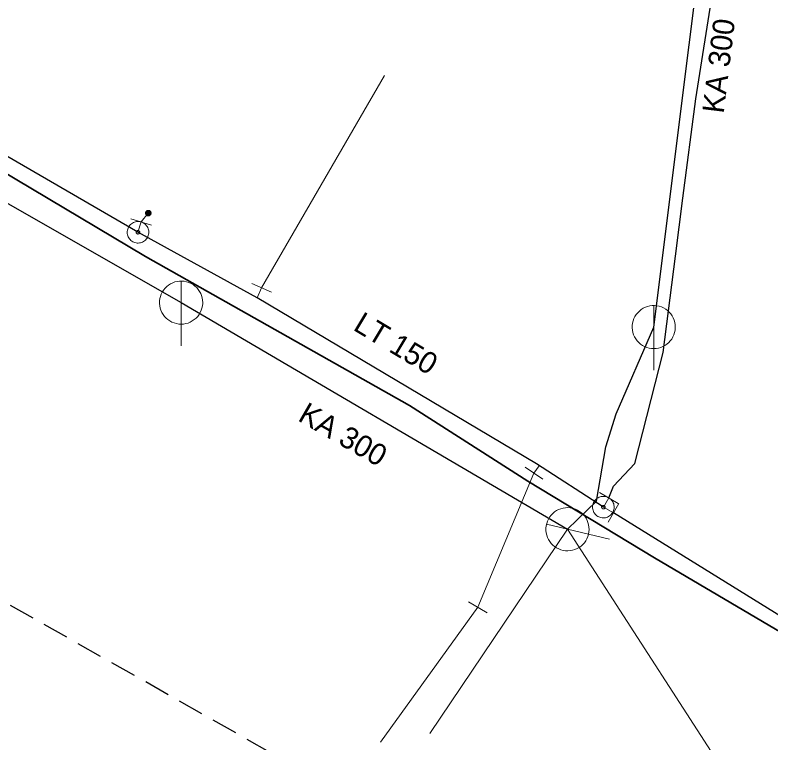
# Model space of a CAD drawing. Extents: x -749365 to -748625, y -965388 to -964881.
# Drawn here: x -749135.59 to -749100.56, y -965043.5 to -965009.76 of the extents above; entities that cross this region are included whole.
import ezdxf

# ---------------------------------------------------------------- set-up
doc = ezdxf.new("R2010")
doc.units = 0
doc.header["$LTSCALE"] = 0.4
doc.linetypes.add('MEDIUM_DASHED', pattern=[4.5, 3, -1.5])
for name, color, linetype, lineweight in [('1', 7, 'MEDIUM_DASHED', 25), ('11', 7, 'Continuous', 13), ('13', 7, 'Continuous', 13), ('14', 7, 'Continuous', 13), ('17', 7, 'Continuous', 25), ('22', 7, 'Continuous', 13), ('34', 7, 'Continuous', 13), ('47', 7, 'Continuous', 13), ('9', 7, 'Continuous', 13)]:
    doc.layers.add(name, color=color, linetype=linetype, lineweight=lineweight)

msp = doc.modelspace()

# ---------------------------------------------------------------- linework, layer by layer
at = {"layer": '1'}
msp.add_lwpolyline([(-748913.896, -965162.751), (-749358.2, -964911.234)], dxfattribs=at)
at = {"layer": '11'}
msp.add_line((-749116.373, -965043.072), (-749109.991, -965033.596), dxfattribs=at)
msp.add_lwpolyline([(-749073.956, -965068.175), (-749091.124, -965052.583), (-749101.388, -965046.912), (-749109.991, -965033.596)], dxfattribs=at)
at = {"layer": '13'}
for p, q in [((-749124.169, -965022.406), (-749118.474, -965012.556)), ((-749111.543, -965031.002), (-749114.141, -965037.213)), ((-749114.141, -965037.213), (-749118.651, -965043.467))]:
    msp.add_line(p, q, dxfattribs=at)
at = {"layer": '14'}
for p, q in [((-749129.75, -965019.352), (-749129.418, -965018.941)), ((-749129.897, -965019.83), (-749129.75, -965019.352)), ((-749124.372, -965022.863), (-749124.169, -965022.406)), ((-749111.304, -965030.651), (-749111.543, -965031.002)), ((-749108.327, -965032.572), (-749108.07, -965032.143)), ((-749108.327, -965032.572), (-749107.856, -965032.835))]:
    msp.add_line(p, q, dxfattribs=at)
at = {"layer": '14', "lineweight": 25}
msp.add_line((-749127.898, -965023.089), (-749109.991, -965033.596), dxfattribs=at)
for points in [[(-749180.034, -964993.011), (-749170.903, -964998.5), (-749127.898, -965023.089)], [(-749105.991, -965024.225), (-749102.71, -964998.031), (-749102.181, -964995.65)], [(-749109.991, -965033.596), (-749108.644, -965032.295), (-749108.214, -965029.781), (-749107.737, -965028.247), (-749105.991, -965024.225)]]:
    msp.add_lwpolyline(points, dxfattribs=at)
at = {"layer": '17'}
for points in [[(-749129.897, -965019.83), (-749141.763, -965012.953), (-749147.67, -965009.555), (-749169.498, -964996.566), (-749174.36, -964993.689), (-749178.686, -964991.22), (-749181.107, -964990.017), (-749187.92, -964986.181), (-749197.61, -964980.691), (-749208.557, -964974.308), (-749219.081, -964968.169), (-749222.514, -964968.719), (-749229.989, -964964.651), (-749252.214, -964952.116), (-749254.966, -964950.395)], [(-749108.07, -965032.143), (-749107.854, -965031.594), (-749106.861, -965030.548), (-749105.556, -965025.399), (-749104.984, -965020.942), (-749104.639, -965018.254), (-749104.048, -965013.641), (-749102.439, -965003.464), (-749102.25, -965001.809), (-749101.848, -964998.641), (-749101.001, -964988.296)], [(-749108.327, -965032.572), (-749111.431, -965030.569), (-749124.372, -965022.863), (-749129.897, -965019.83)], [(-749027.381, -965079.535), (-749031.869, -965076.931), (-749049.479, -965066.729), (-749061.789, -965059.449), (-749067.474, -965056.055), (-749068.21, -965055.686), (-749076.839, -965050.738), (-749082.197, -965048.039), (-749087.923, -965044.562), (-749096.879, -965039.45), (-749099.415, -965038.059), (-749107.856, -965032.835)]]:
    msp.add_lwpolyline(points, dxfattribs=at)
at = {"layer": '17', "lineweight": 35}
msp.add_lwpolyline([(-749218.876, -964969.25), (-749196.521, -964982.106), (-749183.951, -964989.517), (-749175.703, -964993.951), (-749141.565, -965013.806), (-749129.553, -965020.95), (-749117.313, -965027.865), (-749111.826, -965031.374), (-749105.952, -965034.92), (-749090.077, -965044.286), (-749082.192, -965048.943), (-749077.271, -965051.641), (-749068.54, -965056.298), (-749056.263, -965063.706)], dxfattribs=at)
at = {"layer": '22'}
for p, q in [((-749127.898, -965025.089), (-749127.897, -965022.089)), ((-749105.991, -965026.225), (-749105.99, -965023.225)), ((-749108.044, -965034.058), (-749110.963, -965033.364))]:
    msp.add_line(p, q, dxfattribs=at)
for points in [[(-749126.898, -965023.089), (-749126.903, -965022.98), (-749126.921, -965022.872), (-749126.951, -965022.766), (-749126.991, -965022.665), (-749127.043, -965022.568), (-749127.105, -965022.478), (-749127.177, -965022.395), (-749127.257, -965022.321), (-749127.345, -965022.255), (-749127.439, -965022.2), (-749127.539, -965022.155), (-749127.644, -965022.122), (-749127.751, -965022.1), (-749127.86, -965022.09), (-749127.97, -965022.092), (-749128.078, -965022.106), (-749128.185, -965022.131), (-749128.288, -965022.168), (-749128.386, -965022.217), (-749128.478, -965022.275), (-749128.564, -965022.344), (-749128.641, -965022.421), (-749128.71, -965022.507), (-749128.769, -965022.599), (-749128.817, -965022.697), (-749128.854, -965022.8), (-749128.88, -965022.907), (-749128.894, -965023.015), (-749128.897, -965023.125), (-749128.887, -965023.234), (-749128.866, -965023.341), (-749128.832, -965023.445), (-749128.788, -965023.545), (-749128.733, -965023.64), (-749128.667, -965023.728), (-749128.593, -965023.808), (-749128.51, -965023.88), (-749128.42, -965023.942), (-749128.324, -965023.994), (-749128.222, -965024.035), (-749128.117, -965024.065), (-749128.009, -965024.083), (-749127.899, -965024.089), (-749127.79, -965024.083), (-749127.682, -965024.065), (-749127.577, -965024.036), (-749127.475, -965023.995), (-749127.378, -965023.943), (-749127.288, -965023.881), (-749127.205, -965023.81), (-749127.13, -965023.73), (-749127.065, -965023.642), (-749127.009, -965023.548), (-749126.965, -965023.448), (-749126.931, -965023.344), (-749126.909, -965023.236), (-749126.899, -965023.127)], [(-749104.991, -965024.225), (-749104.996, -965024.116), (-749105.014, -965024.008), (-749105.044, -965023.902), (-749105.084, -965023.801), (-749105.136, -965023.704), (-749105.198, -965023.614), (-749105.27, -965023.531), (-749105.35, -965023.457), (-749105.438, -965023.391), (-749105.532, -965023.336), (-749105.632, -965023.291), (-749105.737, -965023.258), (-749105.844, -965023.236), (-749105.953, -965023.226), (-749106.063, -965023.228), (-749106.171, -965023.242), (-749106.278, -965023.267), (-749106.381, -965023.304), (-749106.479, -965023.353), (-749106.571, -965023.411), (-749106.657, -965023.48), (-749106.734, -965023.557), (-749106.803, -965023.643), (-749106.862, -965023.735), (-749106.91, -965023.833), (-749106.947, -965023.936), (-749106.973, -965024.043), (-749106.987, -965024.151), (-749106.99, -965024.261), (-749106.98, -965024.37), (-749106.959, -965024.477), (-749106.925, -965024.581), (-749106.881, -965024.681), (-749106.826, -965024.776), (-749106.76, -965024.864), (-749106.686, -965024.944), (-749106.603, -965025.016), (-749106.513, -965025.078), (-749106.417, -965025.13), (-749106.315, -965025.171), (-749106.21, -965025.201), (-749106.102, -965025.219), (-749105.992, -965025.225), (-749105.883, -965025.219), (-749105.775, -965025.201), (-749105.67, -965025.172), (-749105.568, -965025.131), (-749105.471, -965025.079), (-749105.381, -965025.017), (-749105.298, -965024.946), (-749105.223, -965024.866), (-749105.158, -965024.778), (-749105.102, -965024.684), (-749105.058, -965024.584), (-749105.024, -965024.48), (-749105.002, -965024.372), (-749104.992, -965024.263)], [(-749109.759, -965032.623), (-749109.866, -965032.603), (-749109.975, -965032.596), (-749110.086, -965032.601), (-749110.193, -965032.616), (-749110.299, -965032.644), (-749110.401, -965032.684), (-749110.499, -965032.735), (-749110.589, -965032.795), (-749110.674, -965032.866), (-749110.749, -965032.944), (-749110.816, -965033.031), (-749110.872, -965033.126), (-749110.918, -965033.225), (-749110.953, -965033.329), (-749110.977, -965033.436), (-749110.988, -965033.544), (-749110.989, -965033.654), (-749110.976, -965033.763), (-749110.951, -965033.87), (-749110.916, -965033.973), (-749110.869, -965034.072), (-749110.812, -965034.165), (-749110.744, -965034.252), (-749110.668, -965034.331), (-749110.584, -965034.4), (-749110.492, -965034.46), (-749110.394, -965034.51), (-749110.293, -965034.548), (-749110.186, -965034.576), (-749110.078, -965034.591), (-749109.969, -965034.596), (-749109.86, -965034.587), (-749109.752, -965034.567), (-749109.647, -965034.535), (-749109.546, -965034.492), (-749109.451, -965034.438), (-749109.362, -965034.374), (-749109.281, -965034.301), (-749109.208, -965034.219), (-749109.145, -965034.13), (-749109.091, -965034.034), (-749109.049, -965033.933), (-749109.017, -965033.828), (-749108.998, -965033.72), (-749108.991, -965033.611), (-749108.994, -965033.502), (-749109.011, -965033.394), (-749109.039, -965033.287), (-749109.078, -965033.185), (-749109.128, -965033.088), (-749109.189, -965032.997), (-749109.259, -965032.913), (-749109.338, -965032.837), (-749109.425, -965032.771), (-749109.518, -965032.714), (-749109.618, -965032.667), (-749109.722, -965032.632)]]:
    msp.add_lwpolyline(points, close=True, dxfattribs=at)
at = {"layer": '34'}
for p, q in [((-749130.228, -965019.206), (-749129.272, -965019.498)), ((-749124.626, -965022.203), (-749123.712, -965022.609)), ((-749111.129, -965031.282), (-749111.956, -965030.72)), ((-749108.499, -965031.886), (-749107.641, -965032.4)), ((-749107.612, -965032.398), (-749108.1, -965033.271)), ((-749114.572, -965036.96), (-749113.709, -965037.466))]:
    msp.add_line(p, q, dxfattribs=at)
at = {"layer": '47'}
for points in [[(-749130.335, -965019.589), (-749130.357, -965019.636), (-749130.375, -965019.685), (-749130.387, -965019.736), (-749130.395, -965019.788), (-749130.396, -965019.84), (-749130.392, -965019.893), (-749130.382, -965019.944), (-749130.368, -965019.994), (-749130.349, -965020.042), (-749130.324, -965020.089), (-749130.294, -965020.132), (-749130.26, -965020.172), (-749130.223, -965020.208), (-749130.181, -965020.24), (-749130.137, -965020.268), (-749130.09, -965020.29), (-749130.041, -965020.308), (-749129.989, -965020.32), (-749129.938, -965020.328), (-749129.886, -965020.329), (-749129.833, -965020.325), (-749129.781, -965020.316), (-749129.731, -965020.301), (-749129.683, -965020.282), (-749129.637, -965020.257), (-749129.594, -965020.227), (-749129.553, -965020.194), (-749129.518, -965020.156), (-749129.486, -965020.114), (-749129.458, -965020.07), (-749129.436, -965020.023), (-749129.418, -965019.974), (-749129.405, -965019.923), (-749129.398, -965019.871), (-749129.397, -965019.819), (-749129.4, -965019.767), (-749129.409, -965019.715), (-749129.424, -965019.665), (-749129.444, -965019.616), (-749129.469, -965019.57), (-749129.499, -965019.527), (-749129.532, -965019.487), (-749129.57, -965019.451), (-749129.612, -965019.419), (-749129.656, -965019.391), (-749129.703, -965019.369), (-749129.752, -965019.351), (-749129.802, -965019.338), (-749129.855, -965019.331), (-749129.907, -965019.33), (-749129.959, -965019.333), (-749130.01, -965019.343), (-749130.061, -965019.357), (-749130.109, -965019.377), (-749130.156, -965019.402), (-749130.199, -965019.432), (-749130.238, -965019.465), (-749130.275, -965019.503), (-749130.307, -965019.545)], [(-749129.968, -965019.79), (-749129.973, -965019.798), (-749129.975, -965019.806), (-749129.977, -965019.814), (-749129.978, -965019.822), (-749129.978, -965019.831), (-749129.977, -965019.84), (-749129.976, -965019.848), (-749129.974, -965019.857), (-749129.97, -965019.864), (-749129.967, -965019.872), (-749129.962, -965019.879), (-749129.956, -965019.886), (-749129.95, -965019.891), (-749129.944, -965019.897), (-749129.936, -965019.901), (-749129.928, -965019.906), (-749129.92, -965019.908), (-749129.912, -965019.91), (-749129.904, -965019.911), (-749129.895, -965019.911), (-749129.886, -965019.91), (-749129.878, -965019.909), (-749129.869, -965019.907), (-749129.861, -965019.904), (-749129.854, -965019.9), (-749129.847, -965019.895), (-749129.84, -965019.889), (-749129.835, -965019.883), (-749129.829, -965019.877), (-749129.825, -965019.869), (-749129.82, -965019.861), (-749129.818, -965019.853), (-749129.816, -965019.845), (-749129.815, -965019.837), (-749129.815, -965019.828), (-749129.815, -965019.82), (-749129.817, -965019.811), (-749129.819, -965019.802), (-749129.822, -965019.794), (-749129.826, -965019.787), (-749129.831, -965019.78), (-749129.837, -965019.773), (-749129.843, -965019.768), (-749129.849, -965019.762), (-749129.857, -965019.758), (-749129.865, -965019.753), (-749129.873, -965019.751), (-749129.881, -965019.749), (-749129.889, -965019.748), (-749129.898, -965019.748), (-749129.906, -965019.748), (-749129.915, -965019.75), (-749129.924, -965019.752), (-749129.931, -965019.756), (-749129.939, -965019.759), (-749129.946, -965019.764), (-749129.953, -965019.77), (-749129.958, -965019.776), (-749129.964, -965019.782)], [(-749108.069, -965032.143), (-749108.115, -965032.119), (-749108.164, -965032.099), (-749108.214, -965032.085), (-749108.265, -965032.075), (-749108.318, -965032.072), (-749108.371, -965032.074), (-749108.422, -965032.082), (-749108.473, -965032.094), (-749108.522, -965032.112), (-749108.569, -965032.134), (-749108.614, -965032.162), (-749108.655, -965032.195), (-749108.692, -965032.231), (-749108.726, -965032.271), (-749108.755, -965032.314), (-749108.779, -965032.36), (-749108.799, -965032.409), (-749108.814, -965032.46), (-749108.823, -965032.51), (-749108.826, -965032.563), (-749108.824, -965032.616), (-749108.817, -965032.668), (-749108.804, -965032.719), (-749108.787, -965032.768), (-749108.764, -965032.814), (-749108.736, -965032.859), (-749108.703, -965032.9), (-749108.667, -965032.937), (-749108.627, -965032.971), (-749108.584, -965033), (-749108.538, -965033.024), (-749108.489, -965033.044), (-749108.438, -965033.059), (-749108.388, -965033.068), (-749108.335, -965033.071), (-749108.283, -965033.07), (-749108.231, -965033.063), (-749108.18, -965033.05), (-749108.13, -965033.032), (-749108.084, -965033.009), (-749108.039, -965032.981), (-749107.998, -965032.949), (-749107.961, -965032.912), (-749107.927, -965032.872), (-749107.898, -965032.829), (-749107.874, -965032.783), (-749107.854, -965032.734), (-749107.839, -965032.684), (-749107.83, -965032.633), (-749107.827, -965032.58), (-749107.828, -965032.528), (-749107.836, -965032.476), (-749107.848, -965032.426), (-749107.867, -965032.376), (-749107.889, -965032.329), (-749107.917, -965032.284), (-749107.949, -965032.244), (-749107.986, -965032.206), (-749108.026, -965032.172)], [(-749108.284, -965032.501), (-749108.292, -965032.497), (-749108.3, -965032.494), (-749108.308, -965032.492), (-749108.316, -965032.49), (-749108.325, -965032.49), (-749108.334, -965032.49), (-749108.342, -965032.491), (-749108.351, -965032.493), (-749108.358, -965032.496), (-749108.366, -965032.5), (-749108.374, -965032.505), (-749108.381, -965032.51), (-749108.386, -965032.516), (-749108.392, -965032.522), (-749108.397, -965032.529), (-749108.401, -965032.537), (-749108.404, -965032.545), (-749108.406, -965032.553), (-749108.408, -965032.561), (-749108.408, -965032.57), (-749108.408, -965032.579), (-749108.407, -965032.587), (-749108.405, -965032.596), (-749108.402, -965032.604), (-749108.398, -965032.611), (-749108.393, -965032.619), (-749108.388, -965032.626), (-749108.382, -965032.631), (-749108.376, -965032.637), (-749108.369, -965032.642), (-749108.361, -965032.646), (-749108.353, -965032.649), (-749108.345, -965032.651), (-749108.337, -965032.653), (-749108.328, -965032.653), (-749108.32, -965032.654), (-749108.311, -965032.652), (-749108.302, -965032.65), (-749108.294, -965032.647), (-749108.287, -965032.643), (-749108.279, -965032.638), (-749108.272, -965032.633), (-749108.267, -965032.627), (-749108.261, -965032.621), (-749108.256, -965032.614), (-749108.252, -965032.606), (-749108.249, -965032.598), (-749108.247, -965032.59), (-749108.245, -965032.582), (-749108.245, -965032.573), (-749108.244, -965032.565), (-749108.246, -965032.556), (-749108.248, -965032.547), (-749108.251, -965032.54), (-749108.255, -965032.532), (-749108.26, -965032.524), (-749108.265, -965032.517), (-749108.271, -965032.512), (-749108.277, -965032.506)]]:
    msp.add_lwpolyline(points, close=True, dxfattribs=at)
at = {"layer": '9'}
for points in [[(-749129.544, -965018.941), (-749129.544, -965018.954), (-749129.541, -965018.967), (-749129.539, -965018.98), (-749129.534, -965018.992), (-749129.527, -965019.004), (-749129.521, -965019.015), (-749129.512, -965019.025), (-749129.502, -965019.035), (-749129.492, -965019.043), (-749129.482, -965019.05), (-749129.47, -965019.056), (-749129.458, -965019.061), (-749129.445, -965019.064), (-749129.431, -965019.066), (-749129.419, -965019.068), (-749129.406, -965019.067), (-749129.392, -965019.065), (-749129.38, -965019.062), (-749129.367, -965019.057), (-749129.355, -965019.051), (-749129.345, -965019.044), (-749129.335, -965019.036), (-749129.325, -965019.026), (-749129.316, -965019.016), (-749129.309, -965019.005), (-749129.304, -965018.993), (-749129.299, -965018.981), (-749129.296, -965018.968), (-749129.294, -965018.955), (-749129.291, -965018.942), (-749129.293, -965018.929), (-749129.294, -965018.916), (-749129.298, -965018.903), (-749129.303, -965018.891), (-749129.308, -965018.879), (-749129.316, -965018.868), (-749129.323, -965018.858), (-749129.333, -965018.848), (-749129.343, -965018.84), (-749129.355, -965018.833), (-749129.367, -965018.827), (-749129.379, -965018.822), (-749129.392, -965018.819), (-749129.404, -965018.817), (-749129.418, -965018.816), (-749129.431, -965018.816), (-749129.443, -965018.818), (-749129.456, -965018.821), (-749129.468, -965018.826), (-749129.48, -965018.832), (-749129.492, -965018.839), (-749129.502, -965018.847), (-749129.512, -965018.857), (-749129.519, -965018.867), (-749129.527, -965018.878), (-749129.532, -965018.89), (-749129.538, -965018.902), (-749129.541, -965018.915), (-749129.543, -965018.928)], [(-749129.524, -965018.941), (-749129.524, -965018.952), (-749129.522, -965018.963), (-749129.519, -965018.974), (-749129.516, -965018.984), (-749129.511, -965018.994), (-749129.505, -965019.003), (-749129.497, -965019.012), (-749129.49, -965019.02), (-749129.48, -965019.027), (-749129.472, -965019.033), (-749129.462, -965019.038), (-749129.451, -965019.042), (-749129.441, -965019.045), (-749129.429, -965019.048), (-749129.419, -965019.048), (-749129.407, -965019.048), (-749129.397, -965019.046), (-749129.386, -965019.043), (-749129.375, -965019.039), (-749129.365, -965019.034), (-749129.357, -965019.028), (-749129.348, -965019.021), (-749129.34, -965019.013), (-749129.333, -965019.004), (-749129.326, -965018.995), (-749129.321, -965018.985), (-749129.318, -965018.975), (-749129.315, -965018.964), (-749129.313, -965018.953), (-749129.311, -965018.942), (-749129.311, -965018.931), (-749129.313, -965018.92), (-749129.316, -965018.909), (-749129.321, -965018.899), (-749129.326, -965018.889), (-749129.331, -965018.88), (-749129.338, -965018.871), (-749129.347, -965018.863), (-749129.355, -965018.856), (-749129.365, -965018.85), (-749129.375, -965018.845), (-749129.384, -965018.841), (-749129.396, -965018.838), (-749129.406, -965018.836), (-749129.418, -965018.836), (-749129.429, -965018.835), (-749129.44, -965018.837), (-749129.451, -965018.84), (-749129.46, -965018.844), (-749129.47, -965018.849), (-749129.48, -965018.855), (-749129.489, -965018.862), (-749129.497, -965018.87), (-749129.504, -965018.879), (-749129.509, -965018.888), (-749129.514, -965018.898), (-749129.519, -965018.908), (-749129.522, -965018.919), (-749129.524, -965018.93)], [(-749129.505, -965018.941), (-749129.505, -965018.95), (-749129.504, -965018.959), (-749129.5, -965018.968), (-749129.497, -965018.976), (-749129.494, -965018.984), (-749129.489, -965018.992), (-749129.482, -965018.999), (-749129.477, -965019.005), (-749129.47, -965019.011), (-749129.462, -965019.016), (-749129.453, -965019.02), (-749129.446, -965019.023), (-749129.436, -965019.026), (-749129.428, -965019.027), (-749129.419, -965019.029), (-749129.409, -965019.028), (-749129.401, -965019.027), (-749129.392, -965019.024), (-749129.384, -965019.021), (-749129.375, -965019.017), (-749129.367, -965019.012), (-749129.36, -965019.006), (-749129.355, -965019), (-749129.348, -965018.993), (-749129.343, -965018.985), (-749129.34, -965018.977), (-749129.337, -965018.969), (-749129.333, -965018.96), (-749129.333, -965018.951), (-749129.33, -965018.942), (-749129.331, -965018.933), (-749129.333, -965018.924), (-749129.335, -965018.915), (-749129.338, -965018.907), (-749129.343, -965018.899), (-749129.348, -965018.891), (-749129.353, -965018.884), (-749129.36, -965018.878), (-749129.367, -965018.872), (-749129.375, -965018.867), (-749129.382, -965018.863), (-749129.391, -965018.86), (-749129.399, -965018.857), (-749129.409, -965018.856), (-749129.418, -965018.855), (-749129.426, -965018.855), (-749129.436, -965018.856), (-749129.445, -965018.859), (-749129.453, -965018.862), (-749129.46, -965018.866), (-749129.468, -965018.871), (-749129.475, -965018.877), (-749129.482, -965018.883), (-749129.487, -965018.89), (-749129.492, -965018.898), (-749129.497, -965018.906), (-749129.5, -965018.914), (-749129.502, -965018.923), (-749129.504, -965018.932)], [(-749129.485, -965018.941), (-749129.485, -965018.948), (-749129.483, -965018.955), (-749129.482, -965018.962), (-749129.48, -965018.968), (-749129.477, -965018.974), (-749129.473, -965018.98), (-749129.468, -965018.986), (-749129.463, -965018.991), (-749129.458, -965018.995), (-749129.451, -965018.999), (-749129.446, -965019.002), (-749129.44, -965019.005), (-749129.433, -965019.006), (-749129.426, -965019.009), (-749129.419, -965019.009), (-749129.411, -965019.009), (-749129.404, -965019.007), (-749129.397, -965019.006), (-749129.392, -965019.003), (-749129.384, -965019), (-749129.38, -965018.996), (-749129.374, -965018.992), (-749129.369, -965018.987), (-749129.365, -965018.981), (-749129.36, -965018.975), (-749129.357, -965018.969), (-749129.355, -965018.963), (-749129.353, -965018.956), (-749129.352, -965018.949), (-749129.35, -965018.942), (-749129.35, -965018.935), (-749129.352, -965018.928), (-749129.353, -965018.921), (-749129.357, -965018.915), (-749129.36, -965018.908), (-749129.364, -965018.903), (-749129.367, -965018.897), (-749129.372, -965018.892), (-749129.379, -965018.888), (-749129.384, -965018.884), (-749129.391, -965018.881), (-749129.397, -965018.878), (-749129.404, -965018.876), (-749129.411, -965018.875), (-749129.418, -965018.875), (-749129.424, -965018.875), (-749129.431, -965018.875), (-749129.438, -965018.877), (-749129.445, -965018.88), (-749129.451, -965018.883), (-749129.456, -965018.887), (-749129.463, -965018.891), (-749129.468, -965018.896), (-749129.472, -965018.902), (-749129.475, -965018.907), (-749129.478, -965018.914), (-749129.482, -965018.92), (-749129.482, -965018.927), (-749129.485, -965018.934)], [(-749129.465, -965018.941), (-749129.465, -965018.946), (-749129.465, -965018.951), (-749129.463, -965018.956), (-749129.462, -965018.96), (-749129.46, -965018.965), (-749129.456, -965018.969), (-749129.453, -965018.972), (-749129.45, -965018.976), (-749129.446, -965018.979), (-749129.443, -965018.982), (-749129.438, -965018.984), (-749129.433, -965018.986), (-749129.429, -965018.987), (-749129.424, -965018.989), (-749129.419, -965018.989), (-749129.414, -965018.989), (-749129.409, -965018.988), (-749129.404, -965018.987), (-749129.399, -965018.985), (-749129.394, -965018.983), (-749129.391, -965018.98), (-749129.387, -965018.977), (-749129.384, -965018.973), (-749129.38, -965018.97), (-749129.377, -965018.966), (-749129.375, -965018.961), (-749129.374, -965018.957), (-749129.372, -965018.952), (-749129.372, -965018.947), (-749129.37, -965018.942), (-749129.37, -965018.937), (-749129.372, -965018.932), (-749129.372, -965018.927), (-749129.375, -965018.923), (-749129.377, -965018.918), (-749129.38, -965018.914), (-749129.382, -965018.91), (-749129.386, -965018.907), (-749129.389, -965018.904), (-749129.394, -965018.901), (-749129.399, -965018.899), (-749129.402, -965018.897), (-749129.407, -965018.896), (-749129.413, -965018.895), (-749129.418, -965018.895), (-749129.423, -965018.895), (-749129.428, -965018.896), (-749129.433, -965018.896), (-749129.436, -965018.898), (-749129.441, -965018.9), (-749129.446, -965018.903), (-749129.448, -965018.906), (-749129.453, -965018.909), (-749129.455, -965018.913), (-749129.458, -965018.917), (-749129.46, -965018.922), (-749129.463, -965018.926), (-749129.463, -965018.931), (-749129.465, -965018.936)], [(-749129.445, -965018.941), (-749129.445, -965018.944), (-749129.446, -965018.947), (-749129.445, -965018.949), (-749129.443, -965018.952), (-749129.443, -965018.955), (-749129.441, -965018.957), (-749129.438, -965018.959), (-749129.436, -965018.961), (-749129.434, -965018.963), (-749129.433, -965018.965), (-749129.429, -965018.967), (-749129.426, -965018.968), (-749129.424, -965018.968), (-749129.421, -965018.969), (-749129.419, -965018.969), (-749129.416, -965018.969), (-749129.413, -965018.969), (-749129.409, -965018.968), (-749129.407, -965018.967), (-749129.404, -965018.966), (-749129.402, -965018.964), (-749129.399, -965018.962), (-749129.397, -965018.96), (-749129.397, -965018.958), (-749129.394, -965018.956), (-749129.394, -965018.953), (-749129.392, -965018.95), (-749129.392, -965018.948), (-749129.391, -965018.945), (-749129.389, -965018.942), (-749129.391, -965018.939), (-749129.391, -965018.936), (-749129.392, -965018.933), (-749129.392, -965018.931), (-749129.394, -965018.928), (-749129.396, -965018.926), (-749129.397, -965018.923), (-749129.399, -965018.921), (-749129.402, -965018.92), (-749129.404, -965018.918), (-749129.406, -965018.917), (-749129.409, -965018.916), (-749129.411, -965018.915), (-749129.414, -965018.915), (-749129.418, -965018.914), (-749129.421, -965018.915), (-749129.424, -965018.914), (-749129.426, -965018.916), (-749129.429, -965018.916), (-749129.431, -965018.917), (-749129.433, -965018.919), (-749129.436, -965018.92), (-749129.438, -965018.922), (-749129.44, -965018.925), (-749129.441, -965018.927), (-749129.443, -965018.93), (-749129.443, -965018.932), (-749129.445, -965018.935), (-749129.445, -965018.938)], [(-749129.426, -965018.941), (-749129.426, -965018.943), (-749129.426, -965018.943), (-749129.424, -965018.943), (-749129.424, -965018.945), (-749129.426, -965018.946), (-749129.424, -965018.946), (-749129.424, -965018.946), (-749129.424, -965018.948), (-749129.424, -965018.948), (-749129.423, -965018.949), (-749129.421, -965018.949), (-749129.421, -965018.949), (-749129.421, -965018.95), (-749129.419, -965018.95), (-749129.419, -965018.95), (-749129.418, -965018.95), (-749129.416, -965018.95), (-749129.416, -965018.949), (-749129.416, -965018.949), (-749129.414, -965018.949), (-749129.414, -965018.948), (-749129.414, -965018.948), (-749129.413, -965018.947), (-749129.413, -965018.947), (-749129.411, -965018.946), (-749129.411, -965018.945), (-749129.409, -965018.944), (-749129.409, -965018.944), (-749129.409, -965018.943), (-749129.409, -965018.942), (-749129.409, -965018.941), (-749129.409, -965018.94), (-749129.409, -965018.94), (-749129.411, -965018.939), (-749129.411, -965018.938), (-749129.411, -965018.937), (-749129.411, -965018.937), (-749129.413, -965018.936), (-749129.413, -965018.936), (-749129.414, -965018.935), (-749129.414, -965018.935), (-749129.416, -965018.934), (-749129.416, -965018.934), (-749129.416, -965018.934), (-749129.418, -965018.934), (-749129.419, -965018.934), (-749129.419, -965018.934), (-749129.419, -965018.934), (-749129.421, -965018.935), (-749129.421, -965018.934), (-749129.423, -965018.936), (-749129.423, -965018.936), (-749129.424, -965018.936), (-749129.424, -965018.936), (-749129.424, -965018.938), (-749129.424, -965018.939), (-749129.424, -965018.94), (-749129.426, -965018.94), (-749129.426, -965018.941)]]:
    msp.add_lwpolyline(points, close=True, dxfattribs=at)

# ---------------------------------------------------------------- texts
at = {"layer": '1'}
for s, rotation, p in [('KA 300', 83, (-749102.753, -965014.351)), ('LT 150', 329, (-749119.974, -965024.334)), ('KA 300', 330, (-749122.536, -965028.535))]:
    msp.add_text(s, height=1, rotation=rotation, dxfattribs=at).set_placement(p)

doc.saveas('drawing.dxf')
